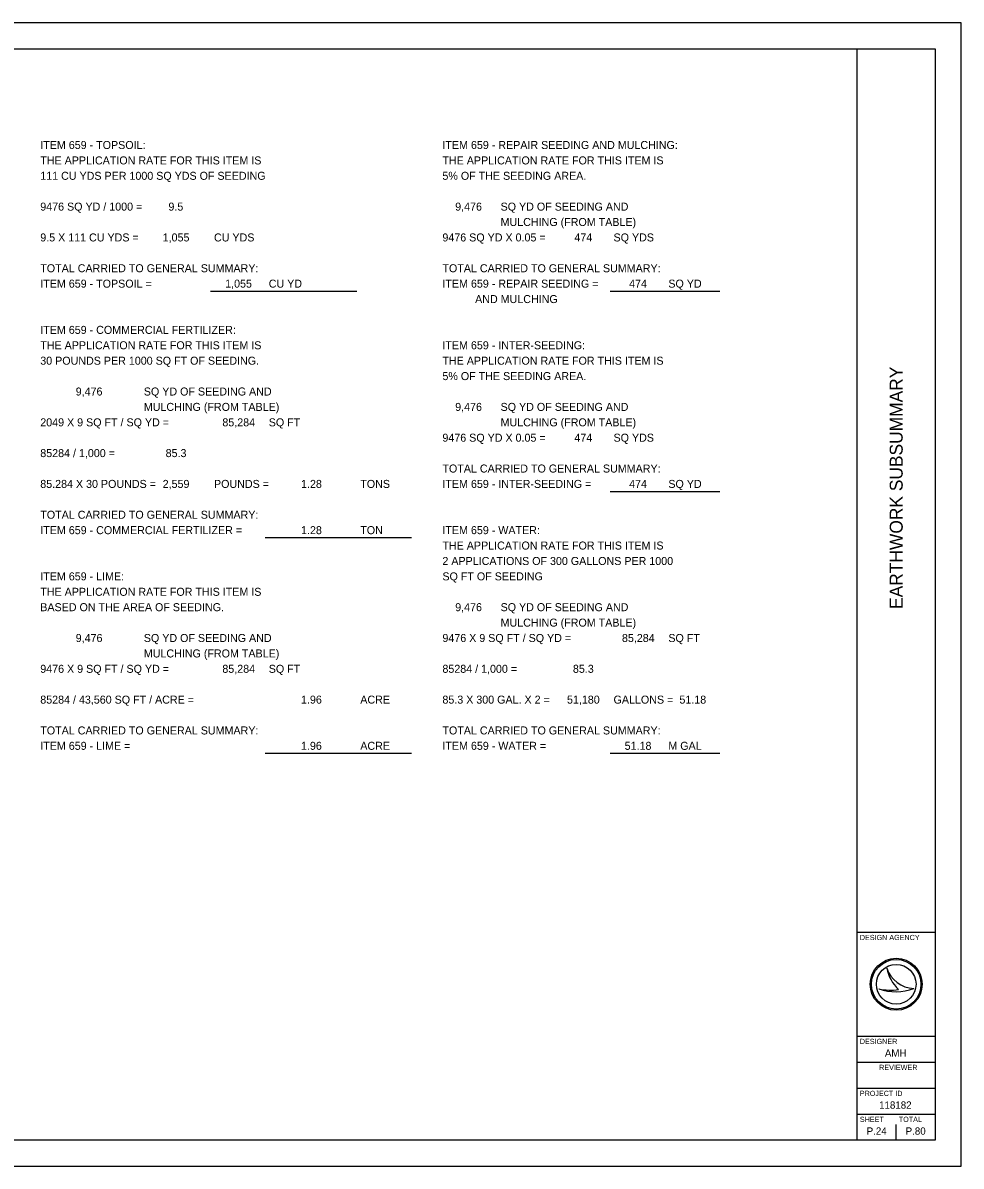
# Model space of a CAD drawing. Extents: x 0 to 34, y 0 to 22.
# Drawn here: x 15.94 to 34, y 0 to 22 of the extents above; entities that cross this region are included whole.
import ezdxf

# ---------------------------------------------------------------- set-up
doc = ezdxf.new("R2010")
doc.units = 0
for name, color, linetype in [('SH_Border', 7, 'Continuous'), ('SH_Cut_Line', 7, 'Continuous'), ('SH_Data', 7, 'Continuous'), ('SH_Text', 7, 'Continuous')]:
    doc.layers.add(name, color=color, linetype=linetype)

msp = doc.modelspace()

# ---------------------------------------------------------------- linework, layer by layer
at = {"layer": 'SH_Border'}
for p, q in [((32, 0.5), (32, 21.5)), ((32, 4.5), (33.5, 4.5)), ((32, 2.5), (33.5, 2.5)), ((32, 2), (33.5, 2)), ((32, 1.5), (33.5, 1.5)), ((32, 1), (33.5, 1))]:
    msp.add_line(p, q, dxfattribs=at)
msp.add_lwpolyline([(1.5, 21.5), (33.5, 21.5), (33.5, 0.5), (1.5, 0.5)], close=True, dxfattribs=at)
at = {"layer": 'SH_Cut_Line'}
msp.add_lwpolyline([(0, 0), (34, 0), (34, 22), (0, 22)], close=True, dxfattribs=at)
at = {"layer": 'SH_Data'}
for p, q in [((32.567, 3.81), (32.567, 3.81)), ((32.417, 3.41), (32.417, 3.41)), ((32.75, 3.5), (32.75, 3.5)), ((33.087, 3.419), (33.087, 3.419)), ((32.375, 0.675), (32.375, 0.675)), ((32.75, 0.5), (32.75, 0.8))]:
    msp.add_line(p, q, dxfattribs=at)
for radius in [0.5, 0.477, 0.477, 0.382]:
    msp.add_circle((32.75, 3.5), radius, dxfattribs=at)
for centre, radius, start, end in [((33.116, 3.998), 0.58, 198.9257, 198.9319), ((33.347, 3.97), 0.796, 191.6379, 191.6421), ((33.116, 3.998), 0.58, 198.9319, 267.1657), ((33.347, 3.97), 0.796, 191.6421, 226.0947), ((32.739, 4.37), 1.013, 251.4576, 290.0832), ((32.648, 4.654), 1.266, 259.4964, 259.4995), ((32.739, 4.37), 1.013, 251.4527, 251.4576), ((32.648, 4.654), 1.266, 259.4995, 276.6672)]:
    msp.add_arc(centre, radius, start, end, dxfattribs=at)
at = {"layer": 'SH_Text'}
for p, q in [((19.552, 16.839), (22.368, 16.839)), ((27.244, 16.839), (29.352, 16.839)), ((27.244, 12.985), (29.352, 12.985)), ((20.606, 12.095), (23.422, 12.095)), ((20.606, 7.945), (23.422, 7.945)), ((27.244, 7.945), (29.352, 7.945))]:
    msp.add_line(p, q, dxfattribs=at)

# ---------------------------------------------------------------- texts
at = {"layer": 'SH_Data'}
msp.add_text('EARTHWORK SUBSUMMARY', height=0.25, rotation=90, dxfattribs=at).set_placement((32.875, 10.722))
for s, height, p in [('DESIGN AGENCY', 0.1, (32.05, 4.35)), ('DESIGNER', 0.1, (32.05, 2.35)), ('AMH', 0.14, (32.532, 2.105)), ('REVIEWER', 0.1, (32.422, 1.85)), ('PROJECT ID', 0.1, (32.05, 1.35)), ('118182', 0.14, (32.421, 1.105)), ('SHEET', 0.1, (32.05, 0.85)), ('TOTAL', 0.1, (32.8, 0.85)), ('P.24', 0.14, (32.182, 0.605)), ('P.80', 0.14, (32.932, 0.605))]:
    msp.add_text(s, height=height, dxfattribs=at).set_placement(p)
at = {"layer": 'SH_Text'}
for s, p in [('ITEM 659 - TOPSOIL:', (16.274, 19.573)), ('ITEM 659 - REPAIR SEEDING AND MULCHING:', (24.015, 19.573)), ('THE APPLICATION RATE FOR THIS ITEM IS', (16.274, 19.276)), ('THE APPLICATION RATE FOR THIS ITEM IS', (24.015, 19.276)), ('111 CU YDS PER 1000 SQ YDS OF SEEDING', (16.274, 18.98)), ('5% OF THE SEEDING AREA.', (24.015, 18.98)), ('9476 SQ YD / 1000 =', (16.274, 18.387)), ('9.5', (18.741, 18.387)), ('9,476', (24.261, 18.387)), ('SQ YD OF SEEDING AND', (25.135, 18.387)), ('MULCHING (FROM TABLE)', (25.135, 18.091)), ('9.5 X 111 CU YDS =', (16.274, 17.794)), ('1,055', (18.63, 17.794)), ('CU YDS', (19.618, 17.794)), ('9476 SQ YD X 0.05 =', (24.015, 17.794)), ('474', (26.555, 17.794)), ('SQ YDS', (27.309, 17.794)), ('TOTAL CARRIED TO GENERAL SUMMARY:', (16.274, 17.201)), ('TOTAL CARRIED TO GENERAL SUMMARY:', (24.015, 17.201)), ('ITEM 659 - TOPSOIL =', (16.274, 16.905)), ('1,055', (19.833, 16.905)), ('CU YD', (20.672, 16.905)), ('ITEM 659 - REPAIR SEEDING =', (24.015, 16.905)), ('474', (27.609, 16.905)), ('SQ YD', (28.364, 16.905)), ('           AND MULCHING', (24.015, 16.608)), ('ITEM 659 - COMMERCIAL FERTILIZER:', (16.274, 16.015)), ('THE APPLICATION RATE FOR THIS ITEM IS', (16.274, 15.719)), ('ITEM 659 - INTER-SEEDING:', (24.015, 15.719)), ('30 POUNDS PER 1000 SQ FT OF SEEDING.', (16.274, 15.422)), ('THE APPLICATION RATE FOR THIS ITEM IS', (24.015, 15.422)), ('5% OF THE SEEDING AREA.', (24.015, 15.126)), ('9,476', (16.956, 14.829)), ('SQ YD OF SEEDING AND', (18.267, 14.829)), ('MULCHING (FROM TABLE)', (18.267, 14.533)), ('9,476', (24.261, 14.533)), ('SQ YD OF SEEDING AND', (25.135, 14.533)), ('2049 X 9 SQ FT / SQ YD =', (16.274, 14.236)), ('85,284', (19.779, 14.236)), ('SQ FT', (20.672, 14.236)), ('MULCHING (FROM TABLE)', (25.135, 14.236)), ('9476 SQ YD X 0.05 =', (24.015, 13.94)), ('474', (26.555, 13.94)), ('SQ YDS', (27.309, 13.94)), ('85284 / 1,000 =', (16.274, 13.644)), ('85.3', (18.687, 13.644)), ('TOTAL CARRIED TO GENERAL SUMMARY:', (24.015, 13.347)), ('85.284 X 30 POUNDS =', (16.274, 13.051)), ('2,559', (18.63, 13.051)), ('POUNDS =', (19.618, 13.051)), ('1.28', (21.294, 13.051)), ('TONS', (22.434, 13.051)), ('ITEM 659 - INTER-SEEDING =', (24.015, 13.051)), ('474', (27.609, 13.051)), ('SQ YD', (28.364, 13.051)), ('TOTAL CARRIED TO GENERAL SUMMARY:', (16.274, 12.458)), ('ITEM 659 - COMMERCIAL FERTILIZER =', (16.274, 12.161)), ('1.28', (21.294, 12.161)), ('TON', (22.434, 12.161)), ('ITEM 659 - WATER:', (24.015, 12.161)), ('THE APPLICATION RATE FOR THIS ITEM IS', (24.015, 11.865)), ('2 APPLICATIONS OF 300 GALLONS PER 1000', (24.015, 11.568)), ('ITEM 659 - LIME:', (16.274, 11.272)), ('SQ FT OF SEEDING', (24.015, 11.272)), ('THE APPLICATION RATE FOR THIS ITEM IS', (16.274, 10.975)), ('BASED ON THE AREA OF SEEDING.', (16.274, 10.679)), ('9,476', (24.261, 10.679)), ('SQ YD OF SEEDING AND', (25.135, 10.679)), ('MULCHING (FROM TABLE)', (25.135, 10.382)), ('9,476', (16.956, 10.086)), ('SQ YD OF SEEDING AND', (18.267, 10.086)), ('9476 X 9 SQ FT / SQ YD =', (24.015, 10.086)), ('85,284', (27.471, 10.086)), ('SQ FT', (28.364, 10.086)), ('MULCHING (FROM TABLE)', (18.267, 9.789)), ('9476 X 9 SQ FT / SQ YD =', (16.274, 9.493)), ('85,284', (19.779, 9.493)), ('SQ FT', (20.672, 9.493)), ('85284 / 1,000 =', (24.015, 9.493)), ('85.3', (26.527, 9.493)), ('85284 / 43,560 SQ FT / ACRE =', (16.274, 8.9)), ('1.96', (21.293, 8.9)), ('ACRE', (22.434, 8.9)), ('85.3 X 300 GAL. X 2 =', (24.015, 8.9)), ('51,180', (26.413, 8.9)), ('GALLONS =', (27.309, 8.9)), ('51.18', (28.577, 8.9)), ('TOTAL CARRIED TO GENERAL SUMMARY:', (16.274, 8.307)), ('TOTAL CARRIED TO GENERAL SUMMARY:', (24.015, 8.307)), ('ITEM 659 - LIME =', (16.274, 8.011)), ('1.96', (21.293, 8.011)), ('ACRE', (22.434, 8.011)), ('ITEM 659 - WATER =', (24.015, 8.011)), ('51.18', (27.523, 8.011)), ('M GAL', (28.364, 8.011))]:
    msp.add_text(s, height=0.154, dxfattribs=at).set_placement(p)

doc.saveas('drawing.dxf')
